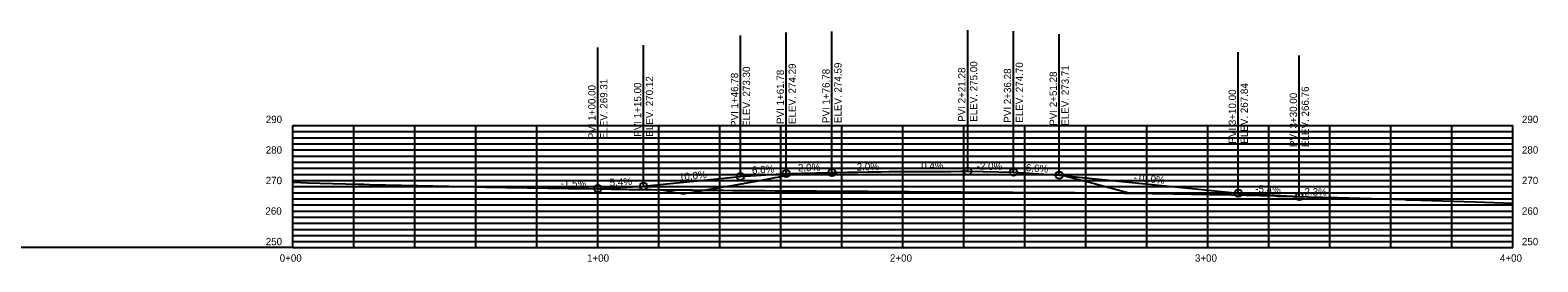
# Model space of a CAD drawing. Extents: x 1709196 to 1718257, y 543790 to 550544.
# Drawn here: x 1710679.2 to 1711173.5, y 543789.6 to 543865.4 of the extents above; entities that cross this region are included whole.
import ezdxf

# ---------------------------------------------------------------- set-up
doc = ezdxf.new("R2010")
doc.units = 0
for name, color, linetype in [('R_Axis', 7, 'Continuous'), ('R_Axis Annot', 7, 'Continuous'), ('R_Exist Surface', 7, 'Continuous'), ('R_Grid', 7, 'Continuous'), ('R_No Plot', 7, 'Continuous'), ('R_Vert Alg', 7, 'Continuous'), ('R_Vert Alg Annot', 7, 'Continuous')]:
    doc.layers.add(name, color=color, linetype=linetype)

msp = doc.modelspace()

# ---------------------------------------------------------------- linework, layer by layer
at = {"layer": 'R_Axis'}
for p, q in [((1710765.3, 543794.19), (1710765.3, 543834.19)), ((1710765.3, 543794.19), (1710765.3, 543834.19)), ((1711165.3, 543794.19), (1711165.3, 543834.19)), ((1711165.3, 543794.19), (1711165.3, 543834.19)), ((1710765.3, 543794.19), (1711165.3, 543794.19)), ((1710765.3, 543794.19), (1711165.3, 543794.19))]:
    msp.add_line(p, q, dxfattribs=at)
at = {"layer": 'R_Exist Surface'}
msp.add_lwpolyline([(1710765.3, 543815.59), (1710767.97, 543815.52), (1710770.06, 543815.47), (1710786.73, 543815.02), (1710788.34, 543814.97), (1710788.53, 543814.97), (1710790.39, 543814.92), (1710790.43, 543814.92), (1710790.43, 543814.92), (1710790.44, 543814.92), (1710811.38, 543814.44), (1710811.38, 543814.44), (1710811.39, 543814.44), (1710821.86, 543814.2), (1710825.25, 543814.12), (1710828.64, 543814.05), (1710832.02, 543813.97), (1710832.07, 543813.97), (1710832.43, 543813.96), (1710835.41, 543813.92), (1710838.8, 543813.87), (1710842.19, 543813.82), (1710845.57, 543813.77), (1710848.96, 543813.72), (1710852.35, 543813.66), (1710853.56, 543813.64), (1710854.37, 543813.63), (1710854.99, 543813.62), (1710855.74, 543813.61), (1710859.12, 543813.56), (1710862.51, 543813.51), (1710865.9, 543813.45), (1710869.28, 543813.4), (1710869.76, 543813.39), (1710872.67, 543813.34), (1710875.58, 543813.28), (1710876.06, 543813.27), (1710876.39, 543813.27), (1710879.45, 543813.24), (1710882.83, 543813.21), (1710886.22, 543813.18), (1710889.61, 543813.15), (1710892.96, 543813.12), (1710893, 543813.12), (1710893.61, 543813.11), (1710896.38, 543813.08), (1710899.77, 543813.05), (1710903.16, 543813.01), (1710906.55, 543812.97), (1710909.6, 543812.94), (1710909.93, 543812.93), (1710911.31, 543812.92), (1710913.32, 543812.91), (1710916.71, 543812.89), (1710920.1, 543812.87), (1710923.48, 543812.85), (1710926.74, 543812.83), (1710926.76, 543812.83), (1710926.87, 543812.83), (1710930.26, 543812.81), (1710933.65, 543812.79), (1710937.03, 543812.76), (1710940.42, 543812.73), (1710942.97, 543812.71), (1710943.51, 543812.71), (1710943.81, 543812.71), (1710947.2, 543812.69), (1710950.58, 543812.67), (1710953.97, 543812.64), (1710957.36, 543812.62), (1710960.74, 543812.6), (1710964.09, 543812.58), (1710964.13, 543812.58), (1710965.67, 543812.56), (1710967.52, 543812.55), (1710970.91, 543812.52), (1710974.29, 543812.5), (1710977.68, 543812.47), (1710981.07, 543812.45), (1710984.46, 543812.42), (1710985.34, 543812.41), (1710986.72, 543812.4), (1710987.84, 543812.38), (1710988.51, 543812.37), (1710991.23, 543812.36), (1710994.62, 543812.34), (1710998.01, 543812.32), (1711001.39, 543812.31), (1711004.78, 543812.29), (1711007.43, 543812.28), (1711008.17, 543812.27), (1711009.15, 543812.25), (1711011.56, 543812.24), (1711014.94, 543812.23), (1711018.33, 543812.21), (1711021.72, 543812.2), (1711025.11, 543812.18), (1711028.49, 543812.17), (1711028.49, 543812.17), (1711047.04, 543811.9), (1711047.51, 543811.89), (1711047.78, 543811.89), (1711065.9, 543811.63), (1711066.81, 543811.62), (1711068.16, 543811.57), (1711087.47, 543811.12), (1711087.91, 543811.12), (1711088.23, 543811.1), (1711107.95, 543810.64), (1711129.92, 543809.91), (1711130.54, 543809.89), (1711131.57, 543809.86), (1711152.98, 543809.16), (1711165.3, 543808.8)], dxfattribs=at)
at = {"layer": 'R_Grid'}
for p, q in [((1710765.3, 543834.19), (1711165.3, 543834.19)), ((1710765.3, 543834.19), (1711165.3, 543834.19)), ((1710765.3, 543832.19), (1711165.3, 543832.19)), ((1710785.3, 543794.19), (1710785.3, 543834.19)), ((1710805.3, 543794.19), (1710805.3, 543834.19)), ((1710825.3, 543794.19), (1710825.3, 543834.19)), ((1710845.3, 543794.19), (1710845.3, 543834.19)), ((1710865.3, 543794.19), (1710865.3, 543834.19)), ((1710885.3, 543794.19), (1710885.3, 543834.19)), ((1710905.3, 543794.19), (1710905.3, 543834.19)), ((1710925.3, 543794.19), (1710925.3, 543834.19)), ((1710945.3, 543794.19), (1710945.3, 543834.19)), ((1710965.3, 543794.19), (1710965.3, 543834.19)), ((1710985.3, 543794.19), (1710985.3, 543834.19)), ((1711005.3, 543794.19), (1711005.3, 543834.19)), ((1711025.3, 543794.19), (1711025.3, 543834.19)), ((1711045.3, 543794.19), (1711045.3, 543834.19)), ((1711065.3, 543794.19), (1711065.3, 543834.19)), ((1711085.3, 543794.19), (1711085.3, 543834.19)), ((1711105.3, 543794.19), (1711105.3, 543834.19)), ((1711125.3, 543794.19), (1711125.3, 543834.19)), ((1711145.3, 543794.19), (1711145.3, 543834.19)), ((1710765.3, 543830.19), (1711165.3, 543830.19)), ((1710765.3, 543828.19), (1711165.3, 543828.19)), ((1710765.3, 543826.19), (1711165.3, 543826.19)), ((1710765.3, 543824.19), (1711165.3, 543824.19)), ((1710765.3, 543822.19), (1711165.3, 543822.19)), ((1710765.3, 543820.19), (1711165.3, 543820.19)), ((1710765.3, 543818.19), (1711165.3, 543818.19)), ((1710765.3, 543816.19), (1711165.3, 543816.19)), ((1710765.3, 543814.19), (1711165.3, 543814.19)), ((1710765.3, 543812.19), (1711165.3, 543812.19)), ((1710765.3, 543810.19), (1711165.3, 543810.19)), ((1710765.3, 543808.19), (1711165.3, 543808.19)), ((1710765.3, 543806.19), (1711165.3, 543806.19)), ((1710765.3, 543804.19), (1711165.3, 543804.19)), ((1710765.3, 543802.19), (1711165.3, 543802.19)), ((1710765.3, 543800.19), (1711165.3, 543800.19)), ((1710765.3, 543798.19), (1711165.3, 543798.19)), ((1710765.3, 543796.19), (1711165.3, 543796.19))]:
    msp.add_line(p, q, dxfattribs=at)
at = {"layer": 'R_No Plot'}
msp.add_line((1710765.3, 543794.19), (1709196.12, 543794.19), dxfattribs=at)
at = {"layer": 'R_Vert Alg'}
for p, q in [((1710880.3, 543814.31), (1710912.08, 543817.49)), ((1710912.08, 543817.49), (1710927.08, 543818.48)), ((1710927.08, 543818.48), (1710942.08, 543818.78)), ((1710986.58, 543819.2), (1711001.58, 543818.9)), ((1711001.58, 543818.9), (1711016.58, 543817.91)), ((1711016.58, 543817.91), (1711075.3, 543812.03)), ((1710865.3, 543813.5), (1710880.3, 543814.31)), ((1711075.3, 543812.03), (1711095.3, 543810.95))]:
    msp.add_line(p, q, dxfattribs=at)
for points in [[(1710885.8, 543813.18), (1710886.22, 543813.1), (1710889.36, 543812.54), (1710889.61, 543812.49), (1710893, 543811.88), (1710893.04, 543811.87), (1710896.38, 543812.4), (1710899.77, 543812.95), (1710900.72, 543813.1), (1710903.16, 543813.51), (1710903.49, 543813.56), (1710906.55, 543814.08), (1710909.93, 543814.66), (1710912.35, 543815.09), (1710913.28, 543815.25), (1710913.32, 543815.26), (1710914.31, 543815.44), (1710914.31, 543815.44), (1710914.32, 543815.44), (1710916.71, 543815.88), (1710918.59, 543816.22), (1710920.1, 543816.51), (1710921.42, 543816.76), (1710923.48, 543817.15), (1710923.49, 543817.15), (1710924.28, 543817.3), (1710926.87, 543817.8), (1710930.26, 543818.46), (1710930.71, 543818.56)], [(1710942.08, 543818.78), (1710942.89, 543818.8), (1710943.7, 543818.81), (1710943.81, 543818.81), (1710947.2, 543818.87), (1710947.24, 543818.87), (1710949.28, 543818.9), (1710949.83, 543818.91), (1710950.03, 543818.91), (1710950.58, 543818.92), (1710953.97, 543818.98), (1710957.36, 543819.04), (1710958.23, 543819.05), (1710960.74, 543819.09), (1710962.47, 543819.12), (1710963.58, 543819.14), (1710964.13, 543819.15), (1710965.29, 543819.17), (1710967.52, 543819.17), (1710970.91, 543819.16), (1710971.79, 543819.16), (1710974.29, 543819.17), (1710976.25, 543819.18), (1710977.68, 543819.18), (1710980.04, 543819.18), (1710981.07, 543819.18), (1710984.46, 543819.2), (1710985.21, 543819.21), (1710985.68, 543819.2), (1710986.58, 543819.2)], [(1711018.54, 543817.71), (1711021.72, 543816.87), (1711022.13, 543816.76), (1711022.58, 543816.64), (1711025.11, 543815.97), (1711028.49, 543815.06), (1711039.89, 543812)]]:
    msp.add_lwpolyline(points, dxfattribs=at)
at = {"layer": 'R_Vert Alg Annot'}
for p, q in [((1710986.58, 543834.2), (1710986.58, 543865.4)), ((1710880.3, 543829.31), (1710880.3, 543860.51)), ((1710912.08, 543832.49), (1710912.08, 543863.69)), ((1710927.08, 543833.48), (1710927.08, 543864.68)), ((1710942.08, 543833.78), (1710942.08, 543864.98)), ((1711001.58, 543833.9), (1711001.58, 543865.1)), ((1711016.58, 543832.91), (1711016.58, 543864.11)), ((1710865.3, 543828.5), (1710865.3, 543859.7)), ((1711075.3, 543827.03), (1711075.3, 543858.23)), ((1711095.3, 543825.95), (1711095.3, 543857.15)), ((1710912.08, 543817.49), (1710912.08, 543832.49)), ((1710927.08, 543818.48), (1710927.08, 543833.48)), ((1710942.08, 543818.78), (1710942.08, 543833.78)), ((1710986.58, 543819.2), (1710986.58, 543834.2)), ((1711001.58, 543818.9), (1711001.58, 543833.9)), ((1711016.58, 543817.91), (1711016.58, 543832.91)), ((1710865.3, 543813.5), (1710865.3, 543828.5)), ((1710880.3, 543814.31), (1710880.3, 543829.31)), ((1711075.3, 543812.03), (1711075.3, 543827.03)), ((1711095.3, 543810.95), (1711095.3, 543825.95))]:
    msp.add_line(p, q, dxfattribs=at)
for centre in [(1710912.08, 543817.49), (1710927.08, 543818.48), (1710942.08, 543818.78), (1710986.58, 543819.2), (1711001.58, 543818.9), (1711016.58, 543817.91), (1710865.3, 543813.5), (1710880.3, 543814.31), (1711075.3, 543812.03), (1711095.3, 543810.95)]:
    msp.add_circle(centre, 1.2, dxfattribs=at)

# ---------------------------------------------------------------- texts
at = {"layer": 'R_Axis Annot'}
for s, height, p in [('290', 2.4, (1710756.42, 543834.99)), ('290', 2.4, (1710756.42, 543834.99)), ('290', 2.4, (1711168.3, 543834.99)), ('290', 2.4, (1711168.3, 543834.99)), ('280', 2.4, (1710756.42, 543824.99)), ('280', 2.4, (1711168.3, 543824.99)), ('270', 2.4, (1710756.42, 543814.99)), ('270', 2.4, (1711168.3, 543814.99)), ('260', 2.4, (1710756.31, 543804.99)), ('260', 2.4, (1711168.3, 543804.99)), ('250', 2.4, (1710756.42, 543794.99)), ('250', 2.4, (1711168.3, 543794.99)), ('0+00', 2.4, (1710761, 543789.59)), ('-', 0.0001, (1710765.3, 543794.19)), ('1+00', 2.4, (1710861.77, 543789.59)), ('2+00', 2.4, (1710961.09, 543789.59)), ('3+00', 2.4, (1711061.09, 543789.59)), ('4+00', 2.4, (1711161.09, 543789.59))]:
    msp.add_text(s, height=height, dxfattribs=at).set_placement(p)
at = {"layer": 'R_Vert Alg Annot'}
for s, rotation, p in [('PVI 1+46.78', 90, (1710911.33, 543833.69)), ('ELEV. 273.30', 90, (1710915.23, 543833.69)), ('PVI 1+61.78', 90, (1710926.33, 543834.68)), ('ELEV. 274.29', 90, (1710930.23, 543834.68)), ('PVI 1+76.78', 90, (1710941.33, 543834.98)), ('ELEV. 274.59', 90, (1710945.23, 543834.98)), ('PVI 2+21.28', 90, (1710985.83, 543835.4)), ('ELEV. 275.00', 90, (1710989.73, 543835.4)), ('PVI 2+36.28', 90, (1711000.83, 543835.1)), ('ELEV. 274.70', 90, (1711004.73, 543835.1)), ('PVI 2+51.28', 90, (1711015.83, 543834.11)), ('ELEV. 273.71', 90, (1711019.73, 543834.11)), ('PVI 1+00.00', 90, (1710864.55, 543829.7)), ('ELEV. 269.31', 90, (1710868.45, 543829.7)), ('PVI 1+15.00', 90, (1710879.55, 543830.51)), ('ELEV. 270.12', 90, (1710883.45, 543830.51)), ('PVI 3+10.00', 90, (1711074.55, 543828.23)), ('ELEV. 267.84', 90, (1711078.45, 543828.23)), ('ELEV. 266.76', 90, (1711098.45, 543827.15)), ('PVI 3+30.00', 90, (1711094.55, 543827.15)), ('6.6%', 3.776, (1710915.91, 543818.35)), ('2.0%', 1.1458, (1710930.95, 543819.16)), ('2.0%', 1.1458, (1710950.21, 543819.43)), ('0.4%', 0.209, (1710971.35, 543819.82)), ('-2.0%', 358.8542, (1710989.49, 543819.74)), ('-6.6%', 356.224, (1711004.51, 543819.3)), ('-1.5%', 359.1313, (1710853.1, 543814.09)), ('5.4%', 3.091, (1710869.25, 543814.32)), ('10.0%', 5.7106, (1710892.04, 543816.09)), ('-10.0%', 354.2894, (1711040.93, 543816.07)), ('-5.4%', 356.909, (1711080.83, 543812.34)), ('2.3%', 358.6573, (1711096.98, 543811.35))]:
    msp.add_text(s, height=2.4, rotation=rotation, dxfattribs=at).set_placement(p)

doc.saveas('drawing.dxf')
